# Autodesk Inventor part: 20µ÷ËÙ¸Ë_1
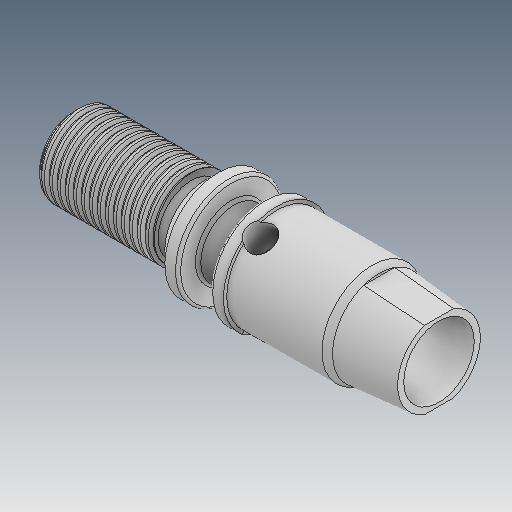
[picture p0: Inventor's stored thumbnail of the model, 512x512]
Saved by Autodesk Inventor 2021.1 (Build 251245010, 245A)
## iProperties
Created: 2019-12
Part Number: 20µ÷ËÙ¸Ë_1
Material: Ogólny
Document SubType Name: Modeling
Designer: user
Density: 1 g/cm^3
Appearance: Domyślna
Author: user
Revision Number: ÈÎºÎ
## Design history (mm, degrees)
feature "ÊäÈë1"
node "Bryła1"
